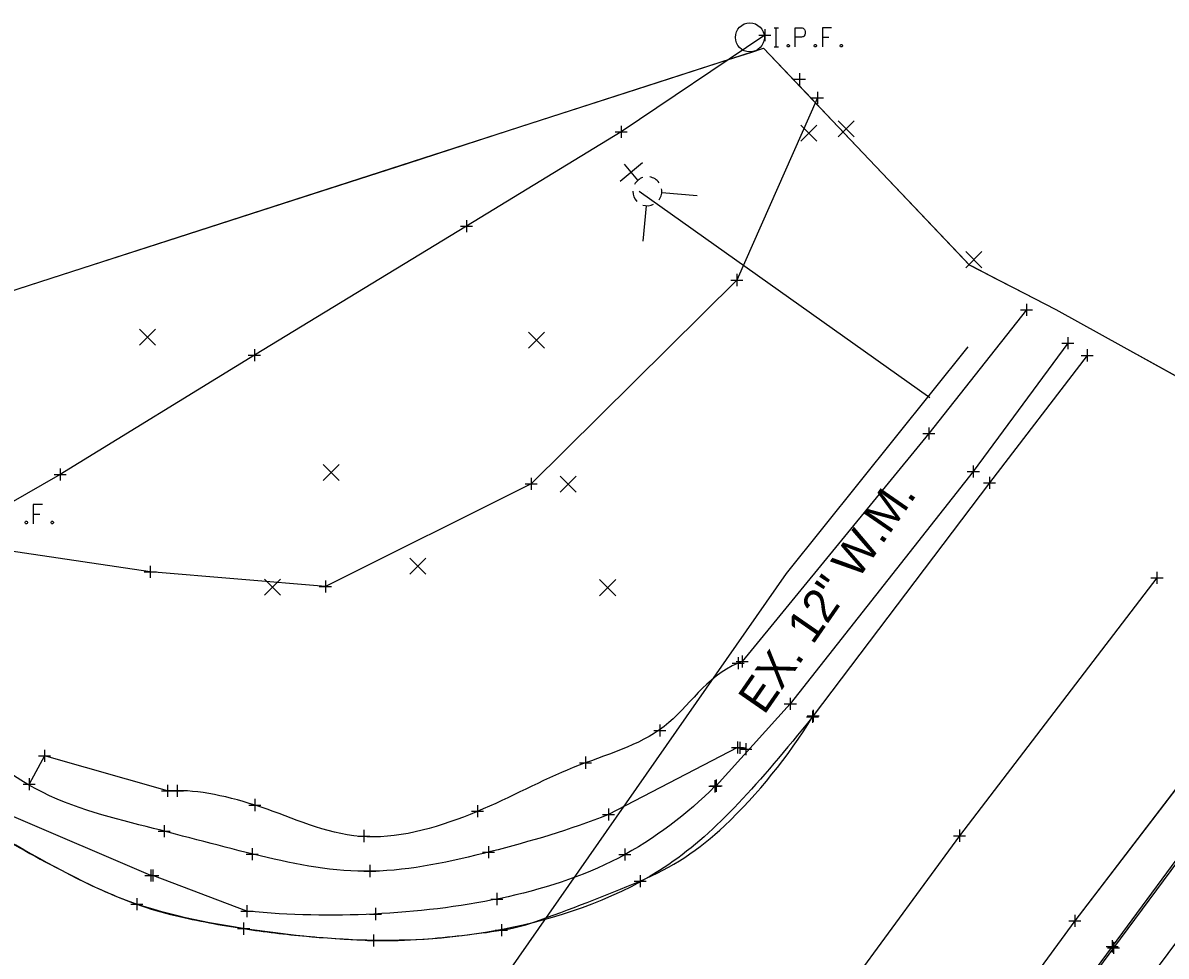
# Model space of a CAD drawing. Extents: x 1324089 to 1329959, y 459099 to 462017.
# Drawn here: x 1324838.9 to 1324933.6, y 459778.4 to 459855.7 of the extents above; entities that cross this region are included whole.
import ezdxf

# ---------------------------------------------------------------- set-up
doc = ezdxf.new("R2010")
doc.units = 0
for name, color, linetype in [('PM_X_Channelizing_Line', 7, 'Continuous'), ('PM_X_Lane_Line', 7, 'Continuous'), ('PM_X_Surveyed_Line', 7, 'Continuous'), ('PV_X_EOP', 7, 'Continuous'), ('PV_X_Shoulder_Aggregate', 7, 'Continuous'), ('RD_X_Fence', 7, 'Continuous'), ('SC_Scratch1', 7, 'Continuous'), ('SV_X_Break_Lines', 7, 'Continuous'), ('SV_X_Mon_Cells_Found', 7, 'Continuous'), ('SV_X_Random_Point', 7, 'Continuous'), ('SV_X_Shot_Marker', 7, 'Continuous'), ('UT_X_Water', 7, 'Continuous'), ('UT_X_Water_Cells', 7, 'Continuous'), ('UT_X_Water_Text', 7, 'Continuous')]:
    doc.layers.add(name, color=color, linetype=linetype)

msp = doc.modelspace()

# ---------------------------------------------------------------- linework, layer by layer
at = {"layer": 'PM_X_Channelizing_Line'}
for p, q in [((1324927.094, 459828.144), (1324919.003, 459817.575)), ((1324919.003, 459817.575), (1324904.391, 459798.27)), ((1324941.456, 459801.398), (1324926.07, 459781.29)), ((1324904.391, 459798.27), (1324904.324, 459798.188)), ((1324926.07, 459781.29), (1324911.552, 459761.479))]:
    msp.add_line(p, q, dxfattribs=at)
for centre, radius, start, end in [((1324866.184, 459821.535), 44.719, 313.60438, 328.528), ((1324881.102, 459805.871), 23.088, 292.77899, 313.60438), ((1324892.193, 459882.175), 108.902, 239.52783, 243.60187), ((1324863.819, 459825.01), 45.083, 243.60187, 249.93573), ((1324825.865, 459937.411), 165.754, 289.52068, 292.77899), ((1324857.43, 459807.518), 26.46, 249.93573, 257.13539), ((1324869.251, 459859.28), 79.556, 257.13539, 261.28574), ((1324876.416, 459794.822), 14.47, 278.47711, 289.52068), ((1324869.999, 459864.157), 84.49, 261.28574, 264.8417), ((1324864.519, 459874.645), 95.175, 274.53203, 278.47711), ((1324870.986, 459875.094), 95.47, 264.8417, 268.18685), ((1324869.13, 459816.468), 36.815, 268.18685, 274.53203)]:
    msp.add_arc(centre, radius, start, end, dxfattribs=at)
at = {"layer": 'PM_X_Lane_Line'}
for p, q in [((1324932.87, 459809.71), (1324916.51, 459788.344)), ((1324916.51, 459788.344), (1324902.102, 459768.67))]:
    msp.add_line(p, q, dxfattribs=at)
at = {"layer": 'PM_X_Surveyed_Line'}
for p, q in [((1324927.094, 459828.144), (1324919.003, 459817.575)), ((1324919.003, 459817.575), (1324904.391, 459798.27)), ((1324932.87, 459809.71), (1324916.51, 459788.344)), ((1324904.391, 459798.27), (1324904.324, 459798.188)), ((1324916.51, 459788.344), (1324902.102, 459768.67))]:
    msp.add_line(p, q, dxfattribs=at)
msp.add_lwpolyline([(1324954.641, 459817.451), (1324941.456, 459801.398), (1324926.07, 459781.29), (1324911.552, 459761.479), (1324896.227, 459740.479), (1324881.923, 459720.032), (1324876.033, 459711.726)], dxfattribs=at)
msp.add_open_spline([(1324904.324, 459798.188), (1324899.836, 459792.655), (1324893.048, 459784.767), (1324879.102, 459780.113), (1324867.894, 459779.372), (1324857.763, 459780.41), (1324847.002, 459782.483), (1324837.422, 459788.17), (1324825.115, 459794.695), (1324818.206, 459802.705), (1324812.359, 459804.289)], degree=3, dxfattribs=at)
at = {"layer": 'PV_X_EOP'}
for p, q in [((1324849.519, 459785.051), (1324837.975, 459790.003)), ((1324849.666, 459785.04), (1324849.519, 459785.051)), ((1324857.475, 459782.086), (1324849.666, 459785.04))]:
    msp.add_line(p, q, dxfattribs=at)
for points in [[(1324925.493, 459829.151), (1324917.653, 459818.519), (1324902.491, 459799.261), (1324896.34, 459792.487), (1324896.243, 459792.434)], [(1324943.904, 459799.154), (1324929.149, 459779.175), (1324914.663, 459759.551), (1324899.438, 459738.467), (1324885.289, 459717.778), (1324874.804, 459702.128)]]:
    msp.add_lwpolyline(points, dxfattribs=at)
msp.add_open_spline([(1324896.243, 459792.434), (1324893.966, 459790.159), (1324888.556, 459785.97), (1324878.572, 459782.829), (1324867.956, 459781.618), (1324861.04, 459781.746), (1324857.475, 459782.086)], degree=3, dxfattribs=at)
at = {"layer": 'PV_X_Shoulder_Aggregate'}
for points in [[(1324898.12, 459795.655), (1324887.432, 459790.1)], [(1324898.806, 459795.503), (1324898.3, 459795.62), (1324898.12, 459795.655)]]:
    msp.add_lwpolyline(points, dxfattribs=at)
msp.add_open_spline([(1324887.432, 459790.1), (1324884.179, 459788.809), (1324877.712, 459786.917), (1324867.7, 459784.728), (1324858.604, 459786.548), (1324849.266, 459789.132), (1324839.115, 459791.532), (1324833.164, 459797.384), (1324829.394, 459798.088)], degree=3, dxfattribs=at)
at = {"layer": 'RD_X_Fence'}
msp.add_lwpolyline([(1324900.387, 459854.68), (1324888.473, 459846.66), (1324875.657, 459838.849), (1324858.085, 459828.168), (1324841.998, 459818.267), (1324833.407, 459813.355)], dxfattribs=at)
at = {"layer": 'SC_Scratch1'}
for p, q in [((1324819.205, 459827.415), (1324900.273, 459853.586)), ((1324900.273, 459853.586), (1324917.321, 459835.643)), ((1324917.321, 459835.643), (1324924.494, 459831.931)), ((1324924.494, 459831.931), (1324955.35, 459814.855))]:
    msp.add_line(p, q, dxfattribs=at)
msp.add_lwpolyline([(1324834.732, 459832.427), (1324842.193, 459834.836), (1324851.709, 459837.908), (1324861.225, 459840.98), (1324870.742, 459844.052), (1324880.258, 459847.124), (1324889.775, 459850.196), (1324897.368, 459852.648), (1324899.291, 459853.269), (1324900.273, 459853.586), (1324904.263, 459849.387), (1324904.566, 459849.068), (1324904.628, 459849.002), (1324906.45, 459847.084), (1324906.67, 459846.853), (1324906.906, 459846.604), (1324913.338, 459839.835), (1324916.97, 459836.013), (1324917.321, 459835.643), (1324917.552, 459835.524), (1324919.131, 459834.707), (1324919.381, 459834.577), (1324921.067, 459833.705), (1324924.494, 459831.931), (1324929.868, 459828.957), (1324938.617, 459824.115)], dxfattribs=at)
at = {"layer": 'SV_X_Break_Lines'}
for p, q in [((1324922.052, 459831.925), (1324913.976, 459821.671)), ((1324913.976, 459821.671), (1324898.492, 459802.774)), ((1324898.492, 459802.774), (1324898.172, 459802.64)), ((1324947.098, 459796.585), (1324932.425, 459776.77)), ((1324840.69, 459794.962), (1324839.424, 459792.609)), ((1324850.88, 459792.059), (1324840.69, 459794.962)), ((1324851.703, 459792.069), (1324850.88, 459792.059))]:
    msp.add_line(p, q, dxfattribs=at)
for points in [[(1324904.744, 459849.47), (1324898.067, 459834.384), (1324881.018, 459817.487), (1324863.969, 459808.996), (1324849.465, 459810.205), (1324836.225, 459812.163), (1324833.407, 459813.355)], [(1324955.625, 459815.009), (1324950.003, 459807.231), (1324943.974, 459798.923), (1324929.276, 459779.062), (1324914.79, 459759.454), (1324899.504, 459738.372), (1324885.441, 459717.683), (1324874.897, 459702.031)]]:
    msp.add_lwpolyline(points, dxfattribs=at)
msp.add_open_spline([(1324898.172, 459802.64), (1324895.447, 459801.499), (1324892.782, 459796.521), (1324884.342, 459794.313), (1324876.888, 459790.135), (1324867.119, 459787.126), (1324859.114, 459790.839), (1324853.868, 459792.093), (1324851.703, 459792.069)], degree=3, dxfattribs=at)
at = {"layer": 'SV_X_Mon_Cells_Found'}
for points in [[(1324901.155, 459855.292), (1324901.508, 459855.292)], [(1324901.332, 459853.692), (1324901.332, 459855.292)], [(1324902.897, 459853.692), (1324902.897, 459855.292), (1324903.426, 459855.292), (1324903.481, 459855.279), (1324903.558, 459855.254), (1324903.591, 459855.229), (1324903.624, 459855.204), (1324903.668, 459855.141), (1324903.702, 459855.078), (1324903.724, 459854.977), (1324903.724, 459854.826), (1324903.713, 459854.775), (1324903.69, 459854.7), (1324903.646, 459854.612), (1324903.602, 459854.574), (1324903.569, 459854.548), (1324903.514, 459854.523), (1324903.426, 459854.511), (1324902.897, 459854.511)], [(1324905.906, 459855.292), (1324905.145, 459855.292), (1324905.145, 459853.692)], [(1324905.145, 459854.511), (1324905.686, 459854.511)], [(1324901.155, 459853.692), (1324901.508, 459853.692)], [(1324902.291, 459853.906), (1324902.346, 459853.906), (1324902.379, 459853.881), (1324902.412, 459853.83), (1324902.412, 459853.767), (1324902.379, 459853.717), (1324902.346, 459853.692), (1324902.291, 459853.692), (1324902.257, 459853.717), (1324902.224, 459853.767), (1324902.224, 459853.83), (1324902.257, 459853.881), (1324902.291, 459853.906)], [(1324904.539, 459853.906), (1324904.594, 459853.906), (1324904.627, 459853.881), (1324904.66, 459853.83), (1324904.66, 459853.767), (1324904.627, 459853.717), (1324904.594, 459853.692), (1324904.539, 459853.692), (1324904.506, 459853.717), (1324904.473, 459853.767), (1324904.473, 459853.83), (1324904.506, 459853.881), (1324904.539, 459853.906)], [(1324906.689, 459853.906), (1324906.744, 459853.906), (1324906.777, 459853.881), (1324906.81, 459853.83), (1324906.81, 459853.767), (1324906.777, 459853.717), (1324906.744, 459853.692), (1324906.689, 459853.692), (1324906.656, 459853.717), (1324906.623, 459853.767), (1324906.623, 459853.83), (1324906.656, 459853.881), (1324906.689, 459853.906)], [(1324840.529, 459815.778), (1324839.768, 459815.778), (1324839.768, 459814.178)], [(1324839.162, 459814.393), (1324839.217, 459814.393), (1324839.25, 459814.367), (1324839.283, 459814.317), (1324839.283, 459814.254), (1324839.25, 459814.204), (1324839.217, 459814.178), (1324839.162, 459814.178), (1324839.129, 459814.204), (1324839.096, 459814.254), (1324839.096, 459814.317), (1324839.129, 459814.367), (1324839.162, 459814.393)], [(1324839.768, 459814.997), (1324840.308, 459814.997)], [(1324841.311, 459814.393), (1324841.367, 459814.393), (1324841.4, 459814.367), (1324841.433, 459814.317), (1324841.433, 459814.254), (1324841.4, 459814.204), (1324841.367, 459814.178), (1324841.311, 459814.178), (1324841.278, 459814.204), (1324841.245, 459814.254), (1324841.245, 459814.317), (1324841.278, 459814.367), (1324841.311, 459814.393)]]:
    msp.add_lwpolyline(points, dxfattribs=at)
msp.add_circle((1324899.141, 459854.492), 1.2, dxfattribs=at)
at = {"layer": 'SV_X_Random_Point'}
for p, q in [((1324906.457, 459846.237), (1324907.791, 459847.573)), ((1324906.457, 459847.573), (1324907.791, 459846.237)), ((1324903.354, 459845.879), (1324904.688, 459847.215)), ((1324903.354, 459847.215), (1324904.688, 459845.879)), ((1324917.027, 459835.407), (1324918.361, 459836.742)), ((1324917.027, 459836.742), (1324918.361, 459835.407)), ((1324848.564, 459828.991), (1324849.897, 459830.326)), ((1324848.564, 459830.326), (1324849.897, 459828.991)), ((1324880.796, 459828.729), (1324882.129, 459830.064)), ((1324880.796, 459830.064), (1324882.129, 459828.729)), ((1324863.781, 459817.773), (1324865.114, 459819.108)), ((1324863.781, 459819.108), (1324865.114, 459817.773)), ((1324883.424, 459816.809), (1324884.758, 459818.144)), ((1324883.424, 459818.144), (1324884.758, 459816.809)), ((1324870.972, 459810.015), (1324872.306, 459811.35)), ((1324870.972, 459811.35), (1324872.306, 459810.015)), ((1324858.925, 459808.265), (1324860.258, 459809.6)), ((1324858.925, 459809.6), (1324860.258, 459808.265)), ((1324886.692, 459808.224), (1324888.025, 459809.559)), ((1324886.692, 459809.559), (1324888.025, 459808.224))]:
    msp.add_line(p, q, dxfattribs=at)
at = {"layer": 'SV_X_Shot_Marker'}
for p, q in [((1324900.387, 459855.18), (1324900.387, 459854.18)), ((1324899.887, 459854.68), (1324900.887, 459854.68)), ((1324900.387, 459854.68), (1324900.387, 459854.68)), ((1324903.244, 459851.514), (1324903.244, 459850.514)), ((1324903.244, 459851.514), (1324903.244, 459850.514)), ((1324902.744, 459851.014), (1324903.744, 459851.014)), ((1324902.744, 459851.014), (1324903.744, 459851.014)), ((1324903.244, 459851.014), (1324903.244, 459851.014)), ((1324903.244, 459851.014), (1324903.244, 459851.014)), ((1324904.244, 459849.47), (1324905.244, 459849.47)), ((1324904.744, 459849.97), (1324904.744, 459848.97)), ((1324904.744, 459849.47), (1324904.744, 459849.47)), ((1324887.973, 459846.66), (1324888.973, 459846.66)), ((1324888.473, 459847.16), (1324888.473, 459846.16)), ((1324888.473, 459846.66), (1324888.473, 459846.66)), ((1324875.157, 459838.849), (1324876.157, 459838.849)), ((1324875.657, 459839.349), (1324875.657, 459838.349)), ((1324875.657, 459838.849), (1324875.657, 459838.849)), ((1324897.567, 459834.384), (1324898.567, 459834.384)), ((1324898.067, 459834.884), (1324898.067, 459833.884)), ((1324898.067, 459834.384), (1324898.067, 459834.384)), ((1324922.052, 459832.425), (1324922.052, 459831.425)), ((1324921.552, 459831.925), (1324922.552, 459831.925)), ((1324922.052, 459831.925), (1324922.052, 459831.925)), ((1324925.493, 459829.651), (1324925.493, 459828.651)), ((1324858.085, 459828.668), (1324858.085, 459827.668)), ((1324924.993, 459829.151), (1324925.993, 459829.151)), ((1324925.493, 459829.151), (1324925.493, 459829.151)), ((1324927.094, 459828.644), (1324927.094, 459827.644)), ((1324857.585, 459828.168), (1324858.585, 459828.168)), ((1324858.085, 459828.168), (1324858.085, 459828.168)), ((1324926.594, 459828.144), (1324927.594, 459828.144)), ((1324927.094, 459828.144), (1324927.094, 459828.144)), ((1324913.976, 459822.171), (1324913.976, 459821.171)), ((1324913.476, 459821.671), (1324914.476, 459821.671)), ((1324913.976, 459821.671), (1324913.976, 459821.671)), ((1324917.653, 459819.019), (1324917.653, 459818.019)), ((1324841.498, 459818.267), (1324842.498, 459818.267)), ((1324841.998, 459818.767), (1324841.998, 459817.767)), ((1324841.998, 459818.267), (1324841.998, 459818.267)), ((1324881.018, 459817.987), (1324881.018, 459816.987)), ((1324917.153, 459818.519), (1324918.153, 459818.519)), ((1324917.653, 459818.519), (1324917.653, 459818.519)), ((1324919.003, 459818.075), (1324919.003, 459817.075)), ((1324880.518, 459817.487), (1324881.518, 459817.487)), ((1324881.018, 459817.487), (1324881.018, 459817.487)), ((1324918.503, 459817.575), (1324919.503, 459817.575)), ((1324919.003, 459817.575), (1324919.003, 459817.575)), ((1324849.465, 459810.705), (1324849.465, 459809.705)), ((1324848.965, 459810.205), (1324849.965, 459810.205)), ((1324849.465, 459810.205), (1324849.465, 459810.205)), ((1324863.969, 459809.496), (1324863.969, 459808.496)), ((1324932.37, 459809.71), (1324933.37, 459809.71)), ((1324932.87, 459810.21), (1324932.87, 459809.21)), ((1324932.87, 459809.71), (1324932.87, 459809.71)), ((1324863.469, 459808.996), (1324864.469, 459808.996)), ((1324863.969, 459808.996), (1324863.969, 459808.996)), ((1324898.172, 459803.14), (1324898.172, 459802.14)), ((1324898.492, 459803.274), (1324898.492, 459802.274)), ((1324897.672, 459802.64), (1324898.672, 459802.64)), ((1324897.992, 459802.774), (1324898.992, 459802.774)), ((1324898.172, 459802.64), (1324898.172, 459802.64)), ((1324898.492, 459802.774), (1324898.492, 459802.774)), ((1324901.991, 459799.261), (1324902.991, 459799.261)), ((1324902.491, 459799.761), (1324902.491, 459798.761)), ((1324902.491, 459799.261), (1324902.491, 459799.261)), ((1324903.824, 459798.188), (1324904.824, 459798.188)), ((1324903.891, 459798.27), (1324904.891, 459798.27)), ((1324904.324, 459798.688), (1324904.324, 459797.688)), ((1324904.324, 459798.188), (1324904.324, 459798.188)), ((1324904.391, 459798.77), (1324904.391, 459797.77)), ((1324904.391, 459798.27), (1324904.391, 459798.27)), ((1324891.678, 459797.557), (1324891.678, 459796.557)), ((1324891.178, 459797.057), (1324892.178, 459797.057)), ((1324891.678, 459797.057), (1324891.678, 459797.057)), ((1324840.69, 459795.462), (1324840.69, 459794.462)), ((1324897.62, 459795.655), (1324898.62, 459795.655)), ((1324897.8, 459795.62), (1324898.8, 459795.62)), ((1324898.12, 459796.155), (1324898.12, 459795.155)), ((1324898.12, 459795.655), (1324898.12, 459795.655)), ((1324898.3, 459796.12), (1324898.3, 459795.12)), ((1324898.3, 459795.62), (1324898.3, 459795.62)), ((1324898.306, 459795.503), (1324899.306, 459795.503)), ((1324898.806, 459796.003), (1324898.806, 459795.003)), ((1324898.806, 459795.503), (1324898.806, 459795.503)), ((1324840.19, 459794.962), (1324841.19, 459794.962)), ((1324840.69, 459794.962), (1324840.69, 459794.962)), ((1324885.032, 459794.393), (1324886.032, 459794.393)), ((1324885.532, 459794.893), (1324885.532, 459793.893)), ((1324885.532, 459794.393), (1324885.532, 459794.393)), ((1324838.924, 459792.609), (1324839.924, 459792.609)), ((1324838.924, 459792.609), (1324839.924, 459792.609)), ((1324839.424, 459793.109), (1324839.424, 459792.109)), ((1324839.424, 459793.109), (1324839.424, 459792.109)), ((1324839.424, 459792.609), (1324839.424, 459792.609)), ((1324839.424, 459792.609), (1324839.424, 459792.609)), ((1324850.88, 459792.559), (1324850.88, 459791.559)), ((1324851.703, 459792.569), (1324851.703, 459791.569)), ((1324895.743, 459792.434), (1324896.743, 459792.434)), ((1324895.84, 459792.487), (1324896.84, 459792.487)), ((1324896.243, 459792.934), (1324896.243, 459791.934)), ((1324896.243, 459792.434), (1324896.243, 459792.434)), ((1324896.34, 459792.987), (1324896.34, 459791.987)), ((1324896.34, 459792.487), (1324896.34, 459792.487)), ((1324850.38, 459792.059), (1324851.38, 459792.059)), ((1324850.88, 459792.059), (1324850.88, 459792.059)), ((1324851.203, 459792.069), (1324852.203, 459792.069)), ((1324851.703, 459792.069), (1324851.703, 459792.069)), ((1324857.625, 459790.887), (1324858.625, 459790.887)), ((1324858.125, 459791.387), (1324858.125, 459790.387)), ((1324858.125, 459790.887), (1324858.125, 459790.887)), ((1324876.57, 459790.881), (1324876.57, 459789.881)), ((1324887.432, 459790.6), (1324887.432, 459789.6)), ((1324876.07, 459790.381), (1324877.07, 459790.381)), ((1324876.57, 459790.381), (1324876.57, 459790.381)), ((1324886.932, 459790.1), (1324887.932, 459790.1)), ((1324887.432, 459790.1), (1324887.432, 459790.1)), ((1324850.103, 459788.723), (1324851.103, 459788.723)), ((1324850.603, 459789.223), (1324850.603, 459788.223)), ((1324850.603, 459788.723), (1324850.603, 459788.723)), ((1324867.165, 459788.818), (1324867.165, 459787.818)), ((1324916.51, 459788.844), (1324916.51, 459787.844)), ((1324866.665, 459788.318), (1324867.665, 459788.318)), ((1324867.165, 459788.318), (1324867.165, 459788.318)), ((1324916.01, 459788.344), (1324917.01, 459788.344)), ((1324916.51, 459788.344), (1324916.51, 459788.344)), ((1324857.414, 459786.823), (1324858.414, 459786.823)), ((1324857.914, 459787.323), (1324857.914, 459786.323)), ((1324857.914, 459786.823), (1324857.914, 459786.823)), ((1324876.995, 459786.984), (1324877.995, 459786.984)), ((1324877.495, 459787.484), (1324877.495, 459786.484)), ((1324877.495, 459786.984), (1324877.495, 459786.984)), ((1324888.283, 459786.781), (1324889.283, 459786.781)), ((1324888.783, 459787.281), (1324888.783, 459786.281)), ((1324888.783, 459786.781), (1324888.783, 459786.781)), ((1324867.657, 459785.916), (1324867.657, 459784.916)), ((1324849.019, 459785.051), (1324850.019, 459785.051)), ((1324849.166, 459785.04), (1324850.166, 459785.04)), ((1324849.519, 459785.551), (1324849.519, 459784.551)), ((1324849.519, 459785.051), (1324849.519, 459785.051)), ((1324849.666, 459785.54), (1324849.666, 459784.54)), ((1324849.666, 459785.04), (1324849.666, 459785.04)), ((1324867.157, 459785.416), (1324868.157, 459785.416)), ((1324867.657, 459785.416), (1324867.657, 459785.416)), ((1324890.041, 459785.084), (1324890.041, 459784.084)), ((1324889.541, 459784.584), (1324890.541, 459784.584)), ((1324890.041, 459784.584), (1324890.041, 459784.584)), ((1324848.352, 459783.163), (1324848.352, 459782.163)), ((1324877.67, 459783.096), (1324878.67, 459783.096)), ((1324878.17, 459783.596), (1324878.17, 459782.596)), ((1324878.17, 459783.096), (1324878.17, 459783.096)), ((1324847.852, 459782.663), (1324848.852, 459782.663)), ((1324848.352, 459782.663), (1324848.352, 459782.663)), ((1324856.975, 459782.086), (1324857.975, 459782.086)), ((1324857.475, 459782.586), (1324857.475, 459781.586)), ((1324857.475, 459782.086), (1324857.475, 459782.086)), ((1324868.13, 459782.355), (1324868.13, 459781.355)), ((1324857.198, 459781.143), (1324857.198, 459780.143)), ((1324867.63, 459781.855), (1324868.63, 459781.855)), ((1324868.13, 459781.855), (1324868.13, 459781.855)), ((1324925.57, 459781.29), (1324926.57, 459781.29)), ((1324926.07, 459781.79), (1324926.07, 459780.79)), ((1324926.07, 459781.29), (1324926.07, 459781.29)), ((1324856.698, 459780.643), (1324857.698, 459780.643)), ((1324857.198, 459780.643), (1324857.198, 459780.643)), ((1324867.965, 459780.171), (1324867.965, 459779.171)), ((1324878.049, 459780.51), (1324879.049, 459780.51)), ((1324878.549, 459781.01), (1324878.549, 459780.01)), ((1324878.549, 459780.51), (1324878.549, 459780.51)), ((1324867.465, 459779.671), (1324868.465, 459779.671)), ((1324867.965, 459779.671), (1324867.965, 459779.671)), ((1324928.649, 459779.175), (1324929.649, 459779.175)), ((1324929.149, 459779.675), (1324929.149, 459778.675)), ((1324929.149, 459779.175), (1324929.149, 459779.175)), ((1324929.276, 459779.562), (1324929.276, 459778.562)), ((1324928.776, 459779.062), (1324929.776, 459779.062)), ((1324929.276, 459779.062), (1324929.276, 459779.062))]:
    msp.add_line(p, q, dxfattribs=at)
at = {"layer": 'UT_X_Water'}
msp.add_line((1324889.977, 459841.745), (1324914.048, 459824.662), dxfattribs=at)
msp.add_lwpolyline([(1324683.283, 459219.357), (1324691.61, 459298.587), (1324698.63, 459347.922), (1324699.63, 459354.943), (1324721.275, 459442.344), (1324756.062, 459540.186), (1324772.185, 459580.087), (1324802.339, 459646.278), (1324825.104, 459690.992), (1324841.263, 459722.731), (1324902.17, 459810.082), (1324917.22, 459828.862)], dxfattribs=at)
at = {"layer": 'UT_X_Water_Cells'}
for p, q in [((1324890.238, 459844.09), (1324888.399, 459842.548)), ((1324889.871, 459842.66), (1324888.766, 459843.978)), ((1324890.646, 459841.739), (1324890.646, 459841.739)), ((1324890.646, 459841.739), (1324890.646, 459841.739)), ((1324891.839, 459841.633), (1324894.768, 459841.378)), ((1324890.543, 459840.545), (1324890.285, 459837.616))]:
    msp.add_line(p, q, dxfattribs=at)
for start, end in [(108.13946, 152.03798), (36.01648, 79.98885), (180.02099, 224.06293), (323.82389, 9.90967), (251.87877, 295.84793)]:
    msp.add_arc((1324890.646, 459841.739), 1.2, start, end, dxfattribs=at)

# ---------------------------------------------------------------- texts
at = {"layer": 'UT_X_Water_Text'}
msp.add_text('EX. 12" W.M.', height=2.8, rotation=55.30797, dxfattribs=at).set_placement((1324900.314, 459798.275))

doc.saveas('drawing.dxf')
